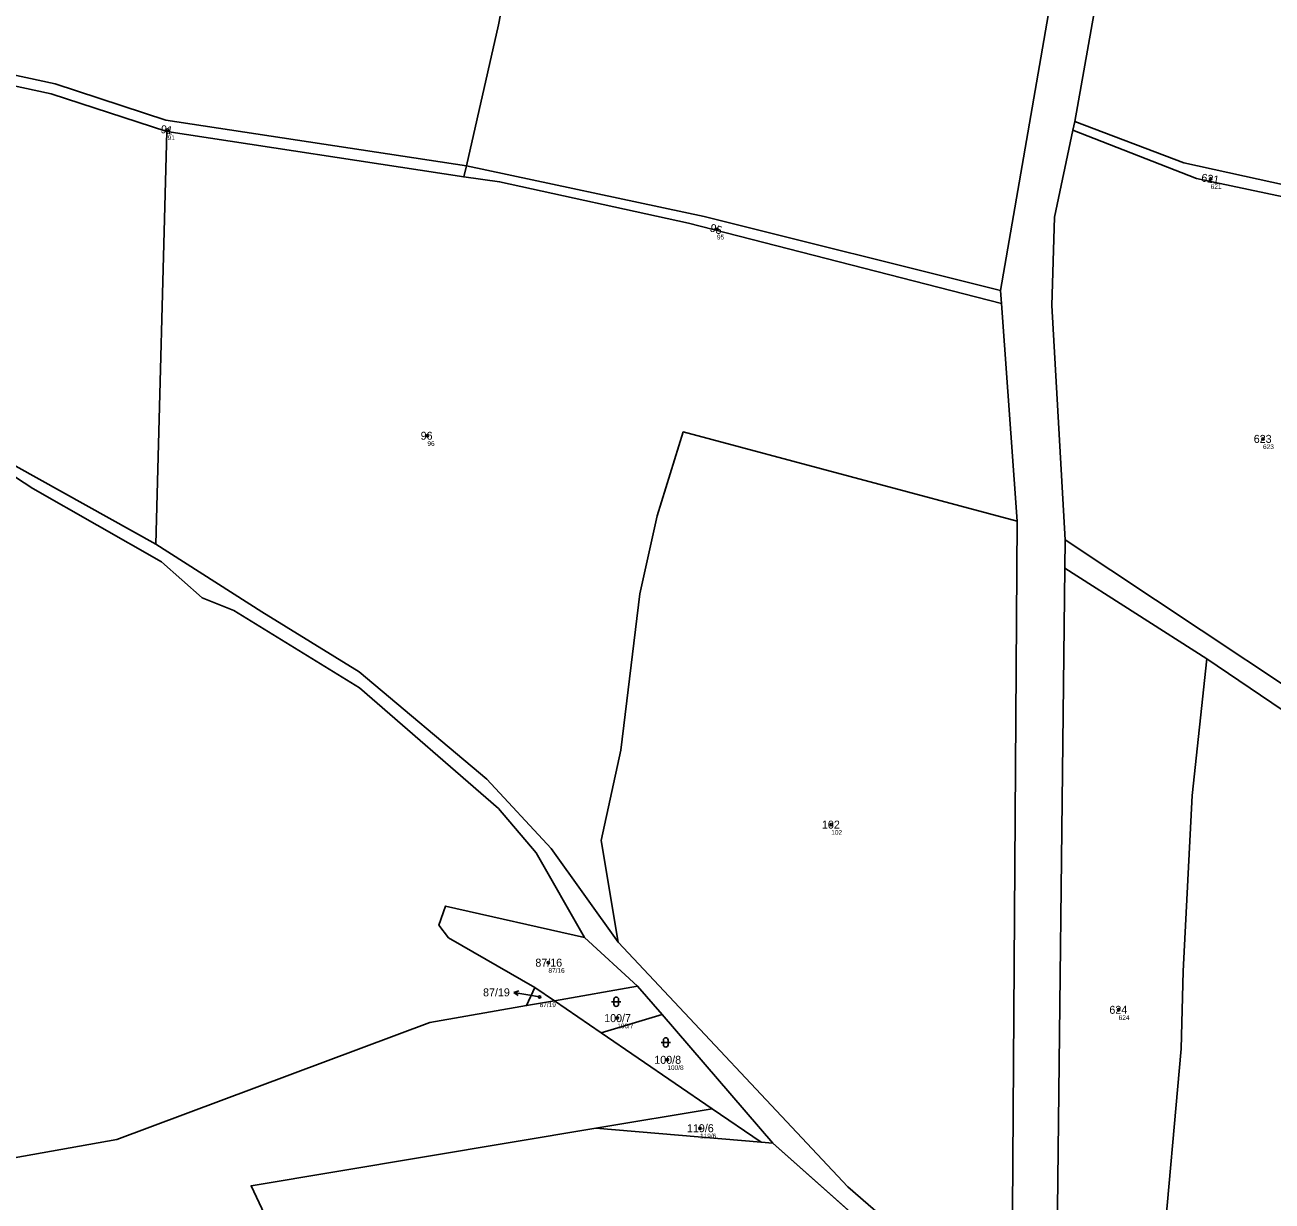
# Model space of a CAD drawing. Extents: x -767985 to -763816, y -1059600 to -1057360.
# Drawn here: x -765597.9 to -765332.9, y -1059313.1 to -1059063.3 of the extents above; entities that cross this region are included whole.
import ezdxf

# ---------------------------------------------------------------- set-up
doc = ezdxf.new("R2010")
doc.units = 0
for name, color, linetype in [('Definiční body', 7, 'Continuous'), ('Hranice parcel', 7, 'Continuous'), ('Parcelní čísla', 7, 'Continuous'), ('Polygon parcely', 7, 'Continuous'), ('Pop  PČ popisy', 7, 'Continuous'), ('Značky kultur', 7, 'Continuous')]:
    doc.layers.add(name, color=color, linetype=linetype)

msp = doc.modelspace()

# ---------------------------------------------------------------- linework, layer by layer
at = {"layer": 'Definiční body'}
for centre in [(-765567.54, -1059085.61994), (-765345.97, -1059096.00994), (-765450.85, -1059106.72994), (-765512.35, -1059150.57994), (-765334.84, -1059151.24994), (-765426.56, -1059233.18994), (-765486.65, -1059262.50994), (-765488.52, -1059269.79994), (-765472.03, -1059274.28994), (-765365.51, -1059272.52994), (-765461.38, -1059283.14994), (-765454.45, -1059297.67994)]:
    msp.add_circle(centre, 0.25, dxfattribs=at)
at = {"layer": 'Hranice parcel'}
for p, q in [((-765567.71, -1059085.97), (-765570.04, -1059173.63)), ((-765567.71, -1059085.97), (-765504.62, -1059095.59)), ((-765375.23, -1059085.67), (-765374.84, -1059083.84)), ((-765504.62, -1059095.59), (-765504.08, -1059093.22)), ((-765390.58, -1059119.7), (-765390.38, -1059122.47)), ((-765390.38, -1059122.47), (-765387.06, -1059168.73)), ((-765376.94, -1059178.73), (-765376.87, -1059172.7)), ((-765376.94, -1059178.73), (-765346.79, -1059197.97)), ((-765467.72, -1059267.5), (-765478.97, -1059257.15)), ((-765489.5, -1059267.79), (-765491.28, -1059271.62)), ((-765489.5, -1059267.79), (-765485.39, -1059270.59)), ((-765485.39, -1059270.59), (-765467.72, -1059267.5)), ((-765462.52, -1059273.53), (-765467.72, -1059267.5)), ((-765485.39, -1059270.59), (-765491.28, -1059271.62)), ((-765475.42, -1059277.39), (-765485.39, -1059270.59)), ((-765475.42, -1059277.39), (-765462.52, -1059273.53)), ((-765438.98, -1059300.82), (-765462.52, -1059273.53)), ((-765451.88, -1059293.53), (-765475.42, -1059277.39)), ((-765476.58, -1059297.67), (-765451.88, -1059293.53)), ((-765451.88, -1059293.53), (-765441.45, -1059300.61)), ((-765441.45, -1059300.61), (-765476.58, -1059297.67)), ((-765441.45, -1059300.61), (-765438.98, -1059300.82)), ((-765387.58, -1059346.55), (-765438.98, -1059300.82))]:
    msp.add_line(p, q, dxfattribs=at)
for points in [[(-765440.47, -1058895.29), (-765390.34, -1058931.94), (-765382.63, -1058938.28), (-765375.83, -1058958.67), (-765370.42, -1058985.9), (-765370.08, -1058997.77), (-765372.5, -1059015.05), (-765390.58, -1059119.7)], [(-765374.84, -1059083.84), (-765365.19, -1059029.54), (-765360.42, -1058999.23), (-765360.24, -1058984.52), (-765361.9, -1058971.13), (-765365.95, -1058957.42), (-765373.97, -1058938.91)], [(-765504.08, -1059093.22), (-765497.25, -1059063.28), (-765489.29, -1059022.4), (-765487.56, -1058986.02)], [(-765504.08, -1059093.22), (-765567.89, -1059083.55), (-765591.46, -1059075.85), (-765627.27, -1059068.13), (-765627.75, -1059070.3)], [(-765627.75, -1059070.3), (-765592.25, -1059077.96), (-765567.71, -1059085.97)], [(-765376.87, -1059172.7), (-765379.7, -1059122.9), (-765379.15, -1059104.14), (-765375.23, -1059085.67)], [(-765375.23, -1059085.67), (-765348.98, -1059095.91), (-765288.71, -1059108.69)], [(-765374.84, -1059083.84), (-765351.64, -1059092.62), (-765288.51, -1059106.47)], [(-765504.08, -1059093.22), (-765453.56, -1059104.04), (-765390.58, -1059119.7)], [(-765504.62, -1059095.59), (-765497.02, -1059096.64), (-765456.89, -1059105.44), (-765390.38, -1059122.47)], [(-765288.71, -1059108.69), (-765291.08, -1059134.96), (-765293.72, -1059180.57), (-765297.32, -1059211.29), (-765299.92, -1059223.82), (-765376.87, -1059172.7)], [(-765640.9, -1059130.1), (-765629, -1059138.49), (-765599.77, -1059157.03), (-765570.04, -1059173.63)], [(-765478.97, -1059257.15), (-765489.25, -1059239.19), (-765497.25, -1059229.77), (-765526.79, -1059204.16), (-765553.49, -1059187.67), (-765560.18, -1059185.01), (-765568.87, -1059177.35), (-765596.2, -1059161.8), (-765641.46, -1059132.18)], [(-765471.82, -1059258.13), (-765475.41, -1059236.57), (-765471.29, -1059217.34), (-765467.25, -1059184.19), (-765463.57, -1059167.57), (-765458, -1059149.78), (-765387.06, -1059168.73)], [(-765387.06, -1059168.73), (-765388.22, -1059336.19), (-765387.95, -1059340.63)], [(-765570.04, -1059173.63), (-765547.53, -1059187.96), (-765526.87, -1059200.72), (-765499.75, -1059223.54), (-765486.1, -1059238.27), (-765471.82, -1059258.13)], [(-765366.93, -1059378.84), (-765372.94, -1059353.06), (-765378.71, -1059333.37), (-765376.94, -1059178.73)], [(-765366.93, -1059378.84), (-765356.3, -1059326), (-765352.23, -1059280.83), (-765351.8, -1059264.33), (-765349.87, -1059227.02), (-765346.79, -1059197.97)], [(-765346.79, -1059197.97), (-765300.99, -1059228.95), (-765298.02, -1059230.75)], [(-765478.97, -1059257.15), (-765508.49, -1059250.49), (-765509.9, -1059254.58), (-765507.86, -1059257.24), (-765489.5, -1059267.79)], [(-765471.82, -1059258.13), (-765423.07, -1059310.14), (-765387.95, -1059340.63)], [(-765491.28, -1059271.62), (-765511.85, -1059275.21), (-765578.33, -1059300.08), (-765624.77, -1059308.36), (-765637.1, -1059286), (-765676.47, -1059296.51)], [(-765544.6, -1059320.89), (-765549.8, -1059309.9), (-765476.58, -1059297.67)]]:
    msp.add_lwpolyline(points, dxfattribs=at)
at = {"layer": 'Polygon parcely'}
for points in [[(-765497.43, -1058805.91), (-765493.76, -1058843.07), (-765488.15, -1058853.88), (-765484.48, -1058857.49), (-765462.22, -1058879.39), (-765440.47, -1058895.29), (-765390.34, -1058931.94), (-765382.63, -1058938.28), (-765375.83, -1058958.67), (-765370.42, -1058985.9), (-765370.08, -1058997.77), (-765372.5, -1059015.05), (-765390.58, -1059119.7), (-765390.38, -1059122.47), (-765387.06, -1059168.73), (-765388.22, -1059336.19)], [(-765387.95, -1059340.63), (-765423.07, -1059310.14), (-765471.82, -1059258.13), (-765486.1, -1059238.27), (-765499.75, -1059223.54), (-765526.87, -1059200.72), (-765547.53, -1059187.96), (-765570.04, -1059173.63), (-765599.77, -1059157.03), (-765629, -1059138.49), (-765640.9, -1059130.1), (-765666.92, -1059108.46), (-765680.9, -1059091.14), (-765693.67, -1059055.19), (-765714.09, -1059004.16), (-765722.72, -1058989.67), (-765736.15, -1058969.84), (-765759.96, -1058951.79), (-765786.46, -1058931.72), (-765811.03, -1058910.71), (-765827, -1058893.49), (-765859.31, -1058812.59)], [(-765378.71, -1059333.37), (-765376.94, -1059178.73), (-765376.87, -1059172.7), (-765379.7, -1059122.9), (-765379.15, -1059104.14), (-765375.23, -1059085.67), (-765374.84, -1059083.84), (-765365.19, -1059029.54), (-765360.42, -1058999.23), (-765360.24, -1058984.52), (-765361.9, -1058971.13), (-765365.95, -1058957.42), (-765373.97, -1058938.91), (-765378.08, -1058929.18), (-765389.18, -1058915.55), (-765416.35, -1058899.74), (-765475.77, -1058847.83), (-765486.57, -1058827.6)], [(-765641.46, -1059132.18), (-765596.2, -1059161.8), (-765568.87, -1059177.35), (-765560.18, -1059185.01), (-765553.49, -1059187.67), (-765526.79, -1059204.16), (-765497.25, -1059229.77), (-765489.25, -1059239.19), (-765478.97, -1059257.15), (-765467.72, -1059267.5), (-765462.52, -1059273.53), (-765438.98, -1059300.82), (-765387.58, -1059346.55)]]:
    msp.add_lwpolyline(points, dxfattribs=at)
for points in [[(-765489.29, -1059022.4), (-765487.56, -1058986.02), (-765556.95, -1058961.89), (-765595.23, -1058946.03), (-765583.01, -1058901.62), (-765618.08, -1058885.57), (-765641.85, -1058877.15), (-765664.72, -1058947.21), (-765670.94, -1058976.19), (-765678.1, -1059002.55), (-765683.19, -1059024.05), (-765693.67, -1059055.19), (-765680.9, -1059091.14), (-765666.92, -1059108.46), (-765640.9, -1059130.1), (-765627.75, -1059070.3), (-765627.27, -1059068.13), (-765591.46, -1059075.85), (-765567.89, -1059083.55), (-765504.08, -1059093.22), (-765497.25, -1059063.28)], [(-765453.56, -1059104.04), (-765390.58, -1059119.7), (-765372.5, -1059015.05), (-765370.08, -1058997.77), (-765370.42, -1058985.9), (-765375.83, -1058958.67), (-765382.63, -1058938.28), (-765390.34, -1058931.94), (-765440.47, -1058895.29), (-765463.85, -1058882.65), (-765469.83, -1058894.61), (-765477.12, -1058912.86), (-765486.74, -1058968.75), (-765487.56, -1058986.02), (-765489.29, -1059022.4), (-765497.25, -1059063.28), (-765504.08, -1059093.22)], [(-765374.84, -1059083.84), (-765351.64, -1059092.62), (-765288.51, -1059106.47), (-765282.8, -1059107.42), (-765247.68, -1058984.6), (-765320.18, -1058953.46), (-765351.76, -1058941.9), (-765373.97, -1058938.91), (-765365.95, -1058957.42), (-765361.9, -1058971.13), (-765360.24, -1058984.52), (-765360.42, -1058999.23), (-765365.19, -1059029.54)], [(-765599.77, -1059157.03), (-765570.04, -1059173.63), (-765567.71, -1059085.97), (-765592.25, -1059077.96), (-765627.75, -1059070.3), (-765640.9, -1059130.1), (-765629, -1059138.49)], [(-765567.71, -1059085.97), (-765504.62, -1059095.59), (-765504.08, -1059093.22), (-765567.89, -1059083.55), (-765591.46, -1059075.85), (-765627.27, -1059068.13), (-765627.75, -1059070.3), (-765592.25, -1059077.96)], [(-765526.87, -1059200.72), (-765499.75, -1059223.54), (-765486.1, -1059238.27), (-765471.82, -1059258.13), (-765475.41, -1059236.57), (-765471.29, -1059217.34), (-765467.25, -1059184.19), (-765463.57, -1059167.57), (-765458, -1059149.78), (-765387.06, -1059168.73), (-765390.38, -1059122.47), (-765456.89, -1059105.44), (-765497.02, -1059096.64), (-765504.62, -1059095.59), (-765567.71, -1059085.97), (-765570.04, -1059173.63), (-765547.53, -1059187.96)], [(-765375.23, -1059085.67), (-765379.15, -1059104.14), (-765379.7, -1059122.9), (-765376.87, -1059172.7), (-765299.92, -1059223.82), (-765297.32, -1059211.29), (-765293.72, -1059180.57), (-765291.08, -1059134.96), (-765288.71, -1059108.69), (-765348.98, -1059095.91)], [(-765348.98, -1059095.91), (-765288.71, -1059108.69), (-765288.51, -1059106.47), (-765351.64, -1059092.62), (-765374.84, -1059083.84), (-765375.23, -1059085.67)], [(-765456.89, -1059105.44), (-765390.38, -1059122.47), (-765390.58, -1059119.7), (-765453.56, -1059104.04), (-765504.08, -1059093.22), (-765504.62, -1059095.59), (-765497.02, -1059096.64)], [(-765293.72, -1059180.57), (-765297.32, -1059211.29), (-765299.92, -1059223.82), (-765376.87, -1059172.7), (-765376.94, -1059178.73), (-765346.79, -1059197.97), (-765300.99, -1059228.95), (-765298.02, -1059230.75), (-765272.38, -1059246.42), (-765236.08, -1059271.23), (-765229.27, -1059275.26), (-765223.11, -1059247.76), (-765222.59, -1059238.4), (-765218.84, -1059207.17), (-765212.03, -1059118.32), (-765223.09, -1059115.76), (-765288.71, -1059108.69), (-765291.08, -1059134.96)], [(-765553.49, -1059187.67), (-765560.18, -1059185.01), (-765568.87, -1059177.35), (-765596.2, -1059161.8), (-765641.46, -1059132.18), (-765676.47, -1059296.51), (-765637.1, -1059286), (-765624.77, -1059308.36), (-765578.33, -1059300.08), (-765511.85, -1059275.21), (-765491.28, -1059271.62), (-765489.5, -1059267.79), (-765507.86, -1059257.24), (-765509.9, -1059254.58), (-765508.49, -1059250.49), (-765478.97, -1059257.15), (-765489.25, -1059239.19), (-765497.25, -1059229.77), (-765526.79, -1059204.16)], [(-765387.95, -1059340.63), (-765388.22, -1059336.19), (-765387.06, -1059168.73), (-765458, -1059149.78), (-765463.57, -1059167.57), (-765467.25, -1059184.19), (-765471.29, -1059217.34), (-765475.41, -1059236.57), (-765471.82, -1059258.13), (-765423.07, -1059310.14)], [(-765349.87, -1059227.02), (-765346.79, -1059197.97), (-765376.94, -1059178.73), (-765378.71, -1059333.37), (-765372.94, -1059353.06), (-765366.93, -1059378.84), (-765356.3, -1059326), (-765352.23, -1059280.83), (-765351.8, -1059264.33)], [(-765306.01, -1059268.92), (-765298.02, -1059230.75), (-765300.99, -1059228.95), (-765346.79, -1059197.97), (-765349.87, -1059227.02), (-765351.8, -1059264.33), (-765352.23, -1059280.83), (-765356.3, -1059326), (-765366.93, -1059378.84), (-765359.21, -1059397.72), (-765352.39, -1059406.52), (-765344.76, -1059412.25), (-765332.65, -1059419.39), (-765330.34, -1059420.24), (-765315.17, -1059350.81)], [(-765489.5, -1059267.79), (-765485.39, -1059270.59), (-765467.72, -1059267.5), (-765478.97, -1059257.15), (-765508.49, -1059250.49), (-765509.9, -1059254.58), (-765507.86, -1059257.24)], [(-765489.5, -1059267.79), (-765491.28, -1059271.62), (-765485.39, -1059270.59)], [(-765462.52, -1059273.53), (-765467.72, -1059267.5), (-765485.39, -1059270.59), (-765475.42, -1059277.39)], [(-765731.36, -1059311.16), (-765753.13, -1059320.96), (-765755.22, -1059334.22), (-765703.99, -1059319.76), (-765685.39, -1059348.97), (-765604.89, -1059331.28), (-765576.01, -1059324.94), (-765544.6, -1059320.89), (-765549.8, -1059309.9), (-765476.58, -1059297.67), (-765451.88, -1059293.53), (-765475.42, -1059277.39), (-765485.39, -1059270.59), (-765491.28, -1059271.62), (-765511.85, -1059275.21), (-765578.33, -1059300.08), (-765624.77, -1059308.36), (-765637.1, -1059286), (-765676.47, -1059296.51)], [(-765438.98, -1059300.82), (-765462.52, -1059273.53), (-765475.42, -1059277.39), (-765451.88, -1059293.53), (-765441.45, -1059300.61)], [(-765451.88, -1059293.53), (-765476.58, -1059297.67), (-765441.45, -1059300.61)], [(-765457.83, -1059330.49), (-765452.53, -1059353.68), (-765451.13, -1059378.41), (-765454.61, -1059402.71), (-765374.21, -1059402.91), (-765376.96, -1059381.51), (-765384.97, -1059355.94), (-765387.58, -1059346.55), (-765438.98, -1059300.82), (-765441.45, -1059300.61), (-765476.58, -1059297.67), (-765549.8, -1059309.9), (-765544.6, -1059320.89), (-765488.23, -1059315.68), (-765463.81, -1059320.99)]]:
    msp.add_lwpolyline(points, close=True, dxfattribs=at)
at = {"layer": 'Pop  PČ popisy'}
for p, q in [((-765493.995, -1059268.829), (-765492.922, -1059268.51)), ((-765491.04, -1059269.35), (-765493.995, -1059268.829)), ((-765493.995, -1059268.829), (-765493.096, -1059269.496)), ((-765488.52, -1059269.8), (-765491.04, -1059269.35))]:
    msp.add_line(p, q, dxfattribs=at)
at = {"layer": 'Značky kultur'}
for p, q in [((-765473.251, -1059270.821), (-765471.249, -1059270.821)), ((-765472.751, -1059270.321), (-765472.751, -1059271.322)), ((-765471.749, -1059271.322), (-765471.749, -1059270.321)), ((-765462.731, -1059279.451), (-765460.729, -1059279.451)), ((-765462.231, -1059278.951), (-765462.231, -1059279.952)), ((-765461.229, -1059279.952), (-765461.229, -1059278.951))]:
    msp.add_line(p, q, dxfattribs=at)
for centre, start, end in [((-765472.25, -1059270.3209), 0, 180), ((-765472.25, -1059271.3209), 180, 359.9878861), ((-765461.73, -1059278.9509), 0, 180), ((-765461.73, -1059279.9509), 180, 359.9878861)]:
    msp.add_arc(centre, 0.5, start, end, dxfattribs=at)

# ---------------------------------------------------------------- texts
at = {"layer": 'Definiční body'}
for s, p in [('91', (-765567.54, -1059087.776)), ('621', (-765345.97, -1059098.166)), ('95', (-765450.85, -1059108.886)), ('96', (-765512.35, -1059152.736)), ('623', (-765334.84, -1059153.406)), ('102', (-765426.56, -1059235.346)), ('87/16', (-765486.65, -1059264.666)), ('87/19', (-765488.52, -1059271.956)), ('624', (-765365.51, -1059274.686)), ('100/7', (-765472.03, -1059276.446)), ('100/8', (-765461.38, -1059285.306)), ('119/6', (-765454.45, -1059299.836))]:
    msp.add_text(s, height=0.999996, dxfattribs=at).set_placement(p)
at = {"layer": 'Parcelní čísla'}
for s, rotation, p in [('91', 351, (-765569.097, -1059086.233)), ('621', 351, (-765348.053, -1059096.54)), ('95', 343, (-765452.477, -1059107.121))]:
    msp.add_text(s, height=1.699998, rotation=rotation, dxfattribs=at).set_placement(p)
for s, p in [('96', (-765513.792, -1059151.43)), ('623', (-765336.814, -1059152.1)), ('102', (-765428.534, -1059234.04)), ('87/16', (-765489.423, -1059263.36)), ('87/19', (-765500.536, -1059269.67)), ('624', (-765367.484, -1059273.38)), ('100/7', (-765474.803, -1059275.14)), ('100/8', (-765464.153, -1059284)), ('119/6', (-765457.223, -1059298.53))]:
    msp.add_text(s, height=1.699998, dxfattribs=at).set_placement(p)

doc.saveas('drawing.dxf')
